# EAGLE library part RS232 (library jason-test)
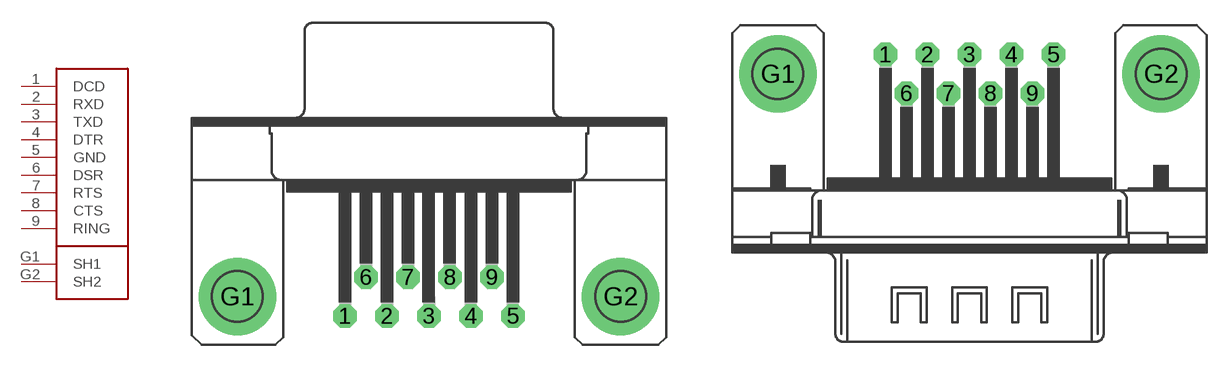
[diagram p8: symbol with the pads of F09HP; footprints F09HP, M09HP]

Designator prefix -

## RS232F  [F09HP]
1  DCD
2  RXD
3  TXD
4  DTR
5  GND  pwr
6  DSR
7  RTS
8  CTS
9  RING
G1  SH1  pwr
G2  SH2  pwr

## RS232M  [M09HP]
Pads as for F09HP

## Footprint F09HP (pad centres in mm)
SUB-D
drill 1.016 octagon: 1 -5.486,-1.27; 2 -2.743,-1.27; 3 0,-1.27; 4 2.743,-1.27; 5 5.486,-1.27; 6 -4.115,1.27; 7 -1.372,1.27; 8 1.372,1.27; 9 4.115,1.27
drill 3.302 pad 5.08 round: G1 -12.522,0; G2 12.522,0

## Footprint M09HP (pad centres in mm)
SUB-D
drill 1.016 octagon: 1 -5.486,1.27; 2 -2.743,1.27; 3 0,1.27; 4 2.743,1.27; 5 5.486,1.27; 6 -4.115,-1.27; 7 -1.372,-1.27; 8 1.372,-1.27; 9 4.115,-1.27
drill 3.302 pad 5.08 round: G1 -12.522,0; G2 12.522,0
